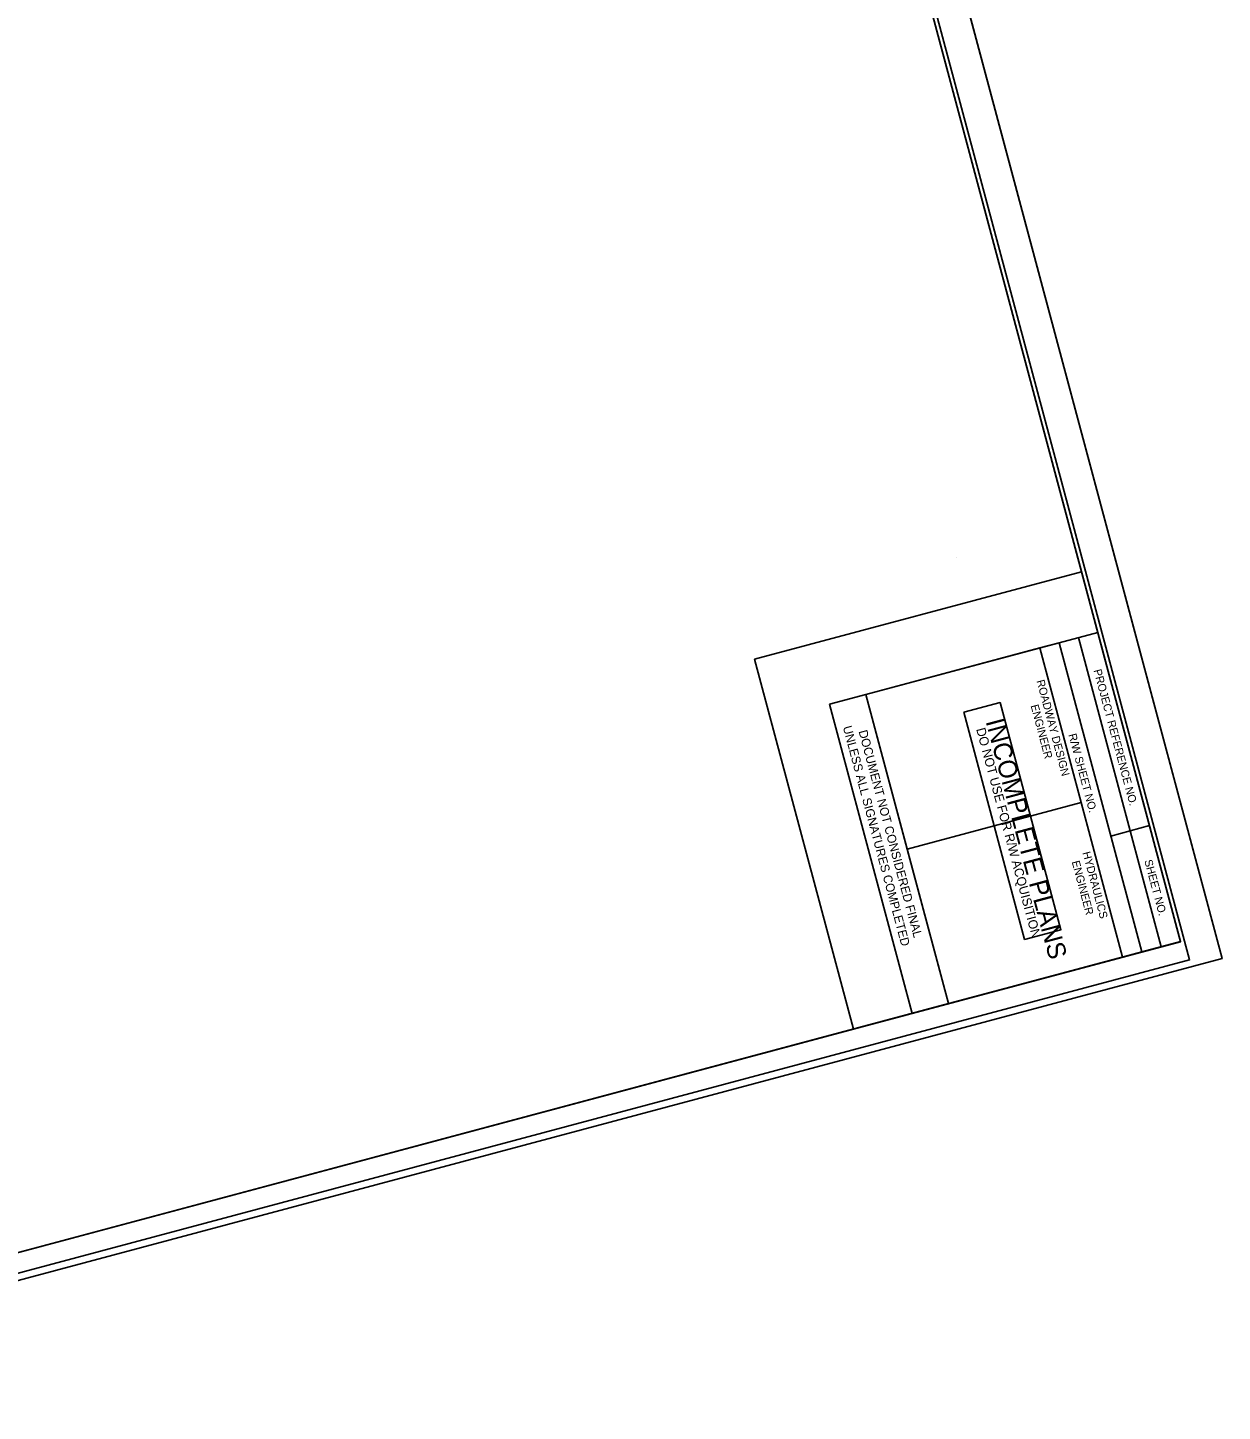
# Model space of a CAD drawing. Extents: x 1617779 to 1622406, y 896496 to 899510.
# Drawn here: x 1621659 to 1622406, y 896496 to 897361 of the extents above; entities that cross this region are included whole.
import ezdxf

# ---------------------------------------------------------------- set-up
doc = ezdxf.new("R2010")
doc.units = 0
for name, color, linetype in [('ControlPoints', 7, 'Continuous'), ('Exist Profile Cell', 7, 'Continuous'), ('Exist Vertical Profile Horizontal Axis Label Major', 7, 'Continuous'), ('Observations', 7, 'Continuous'), ('Prop Horizontal Alignment', 7, 'Continuous'), ('Prop Horizontal Alignment Curve and Spiral Data', 7, 'Continuous'), ('Scratch_Level_4', 7, 'Continuous'), ('Setups', 7, 'Continuous')]:
    doc.layers.add(name, color=color, linetype=linetype)

msp = doc.modelspace()

# ---------------------------------------------------------------- linework, layer by layer
at = {"layer": 'ControlPoints'}
msp.add_lwpolyline([(1620912.77, 898122.23), (1621347.77, 896495.9), (1622405.58, 896778.83), (1621970.59, 898405.16)], close=True, dxfattribs=at)
at = {"layer": 'Exist Profile Cell'}
for p, q in [((1622160.12, 896937.84), (1622182.82, 896943.92)), ((1622160.12, 896937.84), (1622182.82, 896943.92)), ((1622182.82, 896943.92), (1622234.51, 896750.67)), ((1622182.82, 896943.92), (1622234.51, 896750.67)), ((1622211.81, 896744.6), (1622160.12, 896937.84)), ((1622211.81, 896744.6), (1622160.12, 896937.84)), ((1622234.5, 896750.67), (1622211.8, 896744.6)), ((1622234.5, 896750.67), (1622211.8, 896744.6))]:
    msp.add_line(p, q, dxfattribs=at)
at = {"layer": 'Exist Vertical Profile Horizontal Axis Label Major'}
for p, q in [((1622303.55, 896976.22), (1622291.49, 896972.99)), ((1622303.55, 896976.22), (1622355.26, 896782.98)), ((1622303.55, 896976.22), (1622355.26, 896782.98)), ((1622315.66, 896979.47), (1622367.34, 896786.21)), ((1622317.34, 896876.34), (1622208.7, 896847.27)), ((1622360.02, 896861.92), (1622335.88, 896855.41))]:
    msp.add_line(p, q, dxfattribs=at)
for points in [[(1620977.54, 897967.21), (1621991.85, 898238.53), (1622327.79, 896982.7), (1622182.82, 896943.92), (1622234.5, 896750.67), (1621365.12, 896518.14)], [(1622379.47, 896789.42), (1621991.88, 898238.52), (1620977.54, 897967.21), (1621365.12, 896518.14)], [(1622327.79, 896982.7), (1622379.47, 896789.42), (1622355.26, 896782.98), (1622303.55, 896976.22)], [(1622291.49, 896972.99), (1622317.34, 896876.34), (1622208.65, 896847.27), (1622182.82, 896943.92)], [(1622317.34, 896876.34), (1622343.19, 896779.75), (1622234.5, 896750.67), (1622208.65, 896847.27)]]:
    msp.add_lwpolyline(points, close=True, dxfattribs=at)
at = {"layer": 'Observations'}
for points in [[(1621991.85, 898238.53), (1620977.54, 897967.21), (1621365.12, 896518.15), (1622175.16, 896734.81), (1622113.34, 896965.93), (1622317.64, 897020.58)], [(1622113.34, 896965.93), (1622175.16, 896734.79), (1622379.47, 896789.41), (1622317.64, 897020.58)]]:
    msp.add_lwpolyline(points, close=True, dxfattribs=at)
at = {"layer": 'Prop Horizontal Alignment'}
msp.add_line((1622405.58, 896778.83), (1621970.59, 898405.16), dxfattribs=at)
at = {"layer": 'Prop Horizontal Alignment Curve and Spiral Data'}
msp.add_lwpolyline([(1622244.01, 896932.81), (1622266.71, 896938.88), (1622304.69, 896796.88), (1622281.99, 896790.8)], close=True, dxfattribs=at)
at = {"layer": 'Scratch_Level_4'}
msp.add_line((1622239.73, 897029.61), (1622239.73, 897029.61), dxfattribs=at)
at = {"layer": 'Setups'}
msp.add_lwpolyline([(1620935.45, 898114.84), (1621365.93, 896505.43), (1622385.1, 896778.01), (1621954.62, 898387.44)], close=True, dxfattribs=at)

# ---------------------------------------------------------------- texts
at = {"layer": 'Exist Profile Cell'}
for s, p in [('UNLESS ALL SIGNATURES COMPLETED', (1622168.46, 896923.51)), ('UNLESS ALL SIGNATURES COMPLETED', (1622168.46, 896923.51)), ('DOCUMENT NOT CONSIDERED FINAL', (1622178.27, 896920.89)), ('DOCUMENT NOT CONSIDERED FINAL', (1622178.27, 896920.89))]:
    msp.add_text(s, height=5.5, rotation=284.97442, dxfattribs=at).set_placement(p)
at = {"layer": 'Exist Vertical Profile Horizontal Axis Label Major'}
for s, height, p in [('PROJECT REFERENCE NO.', 5.0001, (1622325.09, 896959)), ('ROADWAY DESIGN', 5.0001, (1622289.44, 896952.39)), ('ENGINEER', 5, (1622285.77, 896936.93)), ('R/W SHEET NO.', 5.0001, (1622309.4, 896918.78)), ('ENGINEER', 5, (1622311.46, 896839.34)), ('HYDRAULICS', 5, (1622318.18, 896845.03)), ('SHEET NO.', 5, (1622356.81, 896839.99))]:
    msp.add_text(s, height=height, rotation=284.97442, dxfattribs=at).set_placement(p)
at = {"layer": 'Prop Horizontal Alignment Curve and Spiral Data'}
for s, height, p in [('INCOMPLETE PLANS', 11.52, (1622257.62, 896927.19)), ('DO NOT USE FOR R/W ACQUISITION', 5.76, (1622251.75, 896922.25))]:
    msp.add_text(s, height=height, rotation=284.97442, dxfattribs=at).set_placement(p)

doc.saveas('drawing.dxf')
